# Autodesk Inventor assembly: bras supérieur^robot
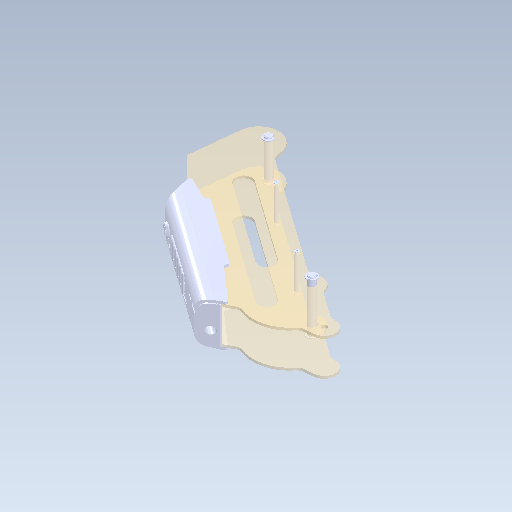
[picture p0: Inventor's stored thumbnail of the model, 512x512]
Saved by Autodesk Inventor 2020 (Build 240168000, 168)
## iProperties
Created: 2018-10
Part Number: bras supérieur^robot
Document SubType Name: Assembly
Designer: bruno
Author: bruno
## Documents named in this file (13)
- C:\Users\bruno\Documents\Systèmes\Mallette Bras robotisé (273265)\Dossier ressources\Maquette Dobot SW2016\bras supérieur^robot.iam
- C:\Users\bruno\Documents\Systèmes\Mallette Bras robotisé (273265)\Dossier ressources\Maquette Dobot SW2016\______43_A.ipt
- C:\Users\bruno\Documents\Systèmes\Mallette Bras robotisé (273265)\Dossier ressources\Maquette Dobot SW2016\_______1_A.ipt
- C:\Users\bruno\Documents\Systèmes\Mallette Bras robotisé (273265)\Dossier ressources\Maquette Dobot SW2016\_________4_A.ipt
- C:\Users\bruno\Documents\Systèmes\Mallette Bras robotisé (273265)\Dossier ressources\Maquette Dobot SW2016\______42_A.ipt
- C:\Users\bruno\Documents\Systèmes\Mallette Bras robotisé (273265)\Dossier ressources\Maquette Dobot SW2016\_____41_A.ipt
- C:\Users\bruno\Documents\Systèmes\Mallette Bras robotisé (273265)\Dossier ressources\Maquette Dobot SW2016\_____40_A.ipt
- C:\Users\bruno\Documents\Systèmes\Mallette Bras robotisé (273265)\Dossier ressources\Maquette Dobot SW2016\_____38_A.ipt
- C:\Users\bruno\Documents\Systèmes\Mallette Bras robotisé (273265)\Dossier ressources\Maquette Dobot SW2016\_____M2_5_A.ipt
- C:\Users\bruno\Documents\Systèmes\Mallette Bras robotisé (273265)\Dossier ressources\Maquette Dobot SW2016\MEER0005_A.ipt
- C:\Users\bruno\Documents\Systèmes\Mallette Bras robotisé (273265)\Dossier ressources\Maquette Dobot SW2016\_______36_A.ipt
- C:\Users\bruno\Documents\Systèmes\Mallette Bras robotisé (273265)\Dossier ressources\Maquette Dobot SW2016\__34_A.ipt
- C:\Users\bruno\Documents\Systèmes\Mallette Bras robotisé (273265)\Dossier ressources\Maquette Dobot SW2016\_______22_A.ipt
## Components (22 placed, 12 different names)
1. ______43_A:1
2. _______1_A:1
3. _________4_A:1
4. _________4_A:2
5. _________4_A:3
6. _________4_A:4
7. ______42_A:1
8. _____41_A:1
9. _____40_A:1
10. _____38_A:1
11. _____M2_5_A:1
12. _____M2_5_A:2
13. _____M2_5_A:3
14. _____M2_5_A:4
15. _____38_A:2
16. MEER0005_A:1
17. MEER0005_A:2
18. _______36_A:1
19. __34_A:1
20. MEER0005_A:3
21. MEER0005_A:4
22. _______22_A:1
